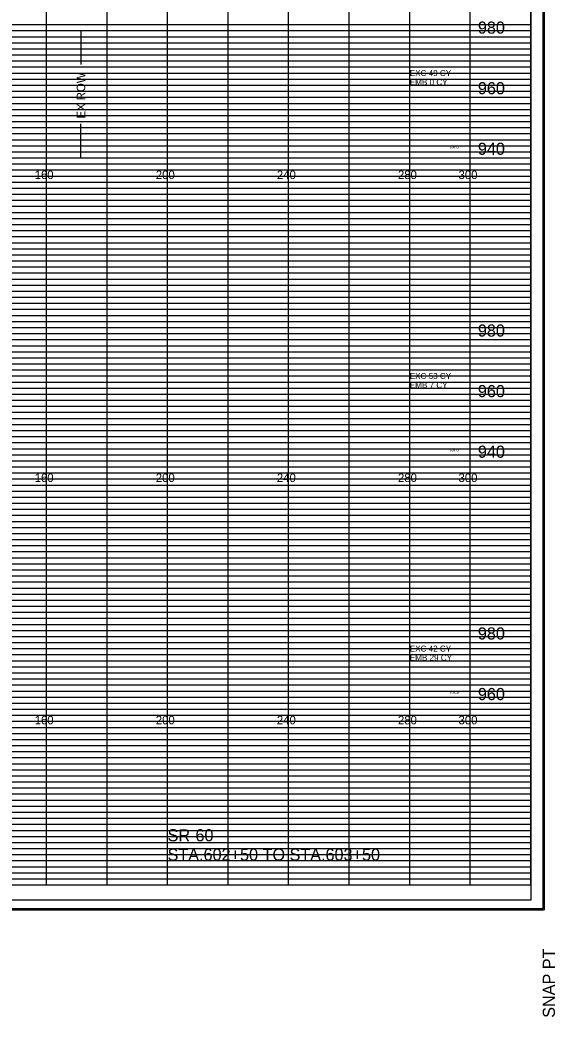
# Model space of a CAD drawing. Extents: x 2313580 to 2322968, y 282099 to 303247.
# Drawn here: x 2318934.9 to 2319111.7, y 287544 to 287873.2 of the extents above; entities that cross this region are included whole.
import ezdxf

# ---------------------------------------------------------------- set-up
doc = ezdxf.new("R2010")
doc.units = 0
for name, color, linetype in [('DESIGN - EARTHWORK - Excavation Limit Lines', 7, 'Continuous'), ('DESIGN - SHEET - Corner Text', 7, 'Continuous'), ('DESIGN - SHEET - Light Grid', 7, 'Continuous'), ('DESIGN - SHEET - Linework', 7, 'Continuous'), ('DESIGN - SHEET - Plot Shape', 7, 'Continuous'), ('DESIGN - TYPICAL - Text', 7, 'Continuous'), ('Prop_ CL text', 7, 'Continuous'), ('SURVEY - PROPERTY - ROW Lines Text', 7, 'Continuous')]:
    doc.layers.add(name, color=color, linetype=linetype)

msp = doc.modelspace()

# ---------------------------------------------------------------- linework, layer by layer
at = {"layer": 'DESIGN - SHEET - Light Grid'}
for p, q in [((2318783.68, 287871.67), (2318943.68, 287871.67)), ((2318783.68, 287869.67), (2318943.68, 287869.67)), ((2318943.68, 287871.67), (2319103.68, 287871.67)), ((2318943.68, 287869.67), (2319103.68, 287869.67)), ((2318783.68, 287865.67), (2318943.68, 287865.67)), ((2318783.68, 287863.67), (2318943.68, 287863.67)), ((2318943.68, 287865.67), (2319103.68, 287865.67)), ((2318943.68, 287863.67), (2319103.68, 287863.67)), ((2318783.68, 287861.67), (2318943.68, 287861.67)), ((2318783.68, 287859.67), (2318943.68, 287859.67)), ((2318943.68, 287861.67), (2319103.68, 287861.67)), ((2318943.68, 287859.67), (2319103.68, 287859.67)), ((2318783.68, 287857.67), (2318943.68, 287857.67)), ((2318943.68, 287857.67), (2319103.68, 287857.67)), ((2318783.68, 287855.67), (2318943.68, 287855.67)), ((2318783.68, 287853.67), (2318943.68, 287853.67)), ((2318943.68, 287855.67), (2319103.68, 287855.67)), ((2318943.68, 287853.67), (2319103.68, 287853.67)), ((2318783.68, 287851.67), (2318943.68, 287851.67)), ((2318783.68, 287849.67), (2318943.68, 287849.67)), ((2318943.68, 287851.67), (2319103.68, 287851.67)), ((2318943.68, 287849.67), (2319103.68, 287849.67)), ((2318783.68, 287845.67), (2318943.68, 287845.67)), ((2318783.68, 287843.67), (2318943.68, 287843.67)), ((2318943.68, 287845.67), (2319103.68, 287845.67)), ((2318943.68, 287843.67), (2319103.68, 287843.67)), ((2318783.68, 287841.67), (2318943.68, 287841.67)), ((2318943.68, 287841.67), (2319103.68, 287841.67)), ((2318783.68, 287839.67), (2318943.68, 287839.67)), ((2318783.68, 287837.67), (2318943.68, 287837.67)), ((2318943.68, 287839.67), (2319103.68, 287839.67)), ((2318943.68, 287837.67), (2319103.68, 287837.67)), ((2318783.68, 287835.67), (2318943.68, 287835.67)), ((2318783.68, 287833.67), (2318943.68, 287833.67)), ((2318943.68, 287835.67), (2319103.68, 287835.67)), ((2318943.68, 287833.67), (2319103.68, 287833.67)), ((2318783.68, 287831.67), (2318943.68, 287831.67)), ((2318943.68, 287831.67), (2319103.68, 287831.67)), ((2318783.68, 287829.67), (2318943.68, 287829.67)), ((2318943.68, 287829.67), (2319103.68, 287829.67)), ((2318783.68, 287825.67), (2318943.68, 287825.67)), ((2318783.68, 287823.67), (2318943.68, 287823.67)), ((2318943.68, 287825.67), (2319103.68, 287825.67)), ((2318943.68, 287823.67), (2319103.68, 287823.67)), ((2318783.68, 287821.67), (2318943.68, 287821.67)), ((2318943.68, 287821.67), (2319103.68, 287821.67)), ((2318783.68, 287819.67), (2318943.68, 287819.67)), ((2318783.68, 287817.67), (2318943.68, 287817.67)), ((2318943.68, 287819.67), (2319103.68, 287819.67)), ((2318943.68, 287817.67), (2319103.68, 287817.67)), ((2318783.68, 287815.67), (2318943.68, 287815.67)), ((2318783.68, 287813.67), (2318943.68, 287813.67)), ((2318943.68, 287815.67), (2319103.68, 287815.67)), ((2318943.68, 287813.67), (2319103.68, 287813.67)), ((2318783.68, 287811.67), (2318943.68, 287811.67)), ((2318943.68, 287811.67), (2319103.68, 287811.67)), ((2318783.68, 287809.67), (2318943.68, 287809.67)), ((2318943.68, 287809.67), (2319103.68, 287809.67)), ((2318783.68, 287805.67), (2318943.68, 287805.67)), ((2318783.68, 287803.67), (2318943.68, 287803.67)), ((2318943.68, 287805.67), (2319103.68, 287805.67)), ((2318943.68, 287803.67), (2319103.68, 287803.67)), ((2318783.68, 287801.67), (2318943.68, 287801.67)), ((2318943.68, 287801.67), (2319103.68, 287801.67)), ((2318783.68, 287799.67), (2318943.68, 287799.67)), ((2318783.68, 287797.67), (2318943.68, 287797.67)), ((2318943.68, 287799.67), (2319103.68, 287799.67)), ((2318943.68, 287797.67), (2319103.68, 287797.67)), ((2318783.68, 287795.67), (2318943.68, 287795.67)), ((2318783.68, 287793.67), (2318943.68, 287793.67)), ((2318943.68, 287795.67), (2319103.68, 287795.67)), ((2318943.68, 287793.67), (2319103.68, 287793.67)), ((2318783.68, 287791.67), (2318943.68, 287791.67)), ((2318943.68, 287791.67), (2319103.68, 287791.67)), ((2318783.68, 287789.67), (2318943.68, 287789.67)), ((2318943.68, 287789.67), (2319103.68, 287789.67)), ((2318783.68, 287785.67), (2318943.68, 287785.67)), ((2318943.68, 287785.67), (2319103.68, 287785.67)), ((2318783.68, 287783.67), (2318943.68, 287783.67)), ((2318783.68, 287781.67), (2318943.68, 287781.67)), ((2318943.68, 287783.67), (2319103.68, 287783.67)), ((2318943.68, 287781.67), (2319103.68, 287781.67)), ((2318783.68, 287779.67), (2318943.68, 287779.67)), ((2318783.68, 287777.67), (2318943.68, 287777.67)), ((2318943.68, 287779.67), (2319103.68, 287779.67)), ((2318943.68, 287777.67), (2319103.68, 287777.67)), ((2318783.68, 287775.67), (2318943.68, 287775.67)), ((2318943.68, 287775.67), (2319103.68, 287775.67)), ((2318783.68, 287773.67), (2318943.68, 287773.67)), ((2318783.68, 287771.67), (2318943.68, 287771.67)), ((2318943.68, 287773.67), (2319103.68, 287773.67)), ((2318943.68, 287771.67), (2319103.68, 287771.67)), ((2318783.68, 287769.67), (2318943.68, 287769.67)), ((2318943.68, 287769.67), (2319103.68, 287769.67)), ((2318783.68, 287765.67), (2318943.68, 287765.67)), ((2318943.68, 287765.67), (2319103.68, 287765.67)), ((2318783.68, 287763.67), (2318943.68, 287763.67)), ((2318783.68, 287761.67), (2318943.68, 287761.67)), ((2318943.68, 287763.67), (2319103.68, 287763.67)), ((2318943.68, 287761.67), (2319103.68, 287761.67)), ((2318783.68, 287759.67), (2318943.68, 287759.67)), ((2318783.68, 287757.67), (2318943.68, 287757.67)), ((2318943.68, 287759.67), (2319103.68, 287759.67)), ((2318943.68, 287757.67), (2319103.68, 287757.67)), ((2318783.68, 287755.67), (2318943.68, 287755.67)), ((2318943.68, 287755.67), (2319103.68, 287755.67)), ((2318783.68, 287753.67), (2318943.68, 287753.67)), ((2318783.68, 287751.67), (2318943.68, 287751.67)), ((2318943.68, 287753.67), (2319103.68, 287753.67)), ((2318943.68, 287751.67), (2319103.68, 287751.67)), ((2318783.68, 287749.67), (2318943.68, 287749.67)), ((2318943.68, 287749.67), (2319103.68, 287749.67)), ((2318783.68, 287745.67), (2318943.68, 287745.67)), ((2318943.68, 287745.67), (2319103.68, 287745.67)), ((2318783.68, 287743.67), (2318943.68, 287743.67)), ((2318783.68, 287741.67), (2318943.68, 287741.67)), ((2318943.68, 287743.67), (2319103.68, 287743.67)), ((2318943.68, 287741.67), (2319103.68, 287741.67)), ((2318783.68, 287739.67), (2318943.68, 287739.67)), ((2318783.68, 287737.67), (2318943.68, 287737.67)), ((2318943.68, 287739.67), (2319103.68, 287739.67)), ((2318943.68, 287737.67), (2319103.68, 287737.67)), ((2318783.68, 287735.67), (2318943.68, 287735.67)), ((2318943.68, 287735.67), (2319103.68, 287735.67)), ((2318783.68, 287733.67), (2318943.68, 287733.67)), ((2318783.68, 287731.67), (2318943.68, 287731.67)), ((2318943.68, 287733.67), (2319103.68, 287733.67)), ((2318943.68, 287731.67), (2319103.68, 287731.67)), ((2318783.68, 287729.67), (2318943.68, 287729.67)), ((2318943.68, 287729.67), (2319103.68, 287729.67)), ((2318783.68, 287725.67), (2318943.68, 287725.67)), ((2318943.68, 287725.67), (2319103.68, 287725.67)), ((2318783.68, 287723.67), (2318943.68, 287723.67)), ((2318783.68, 287721.67), (2318943.68, 287721.67)), ((2318943.68, 287723.67), (2319103.68, 287723.67)), ((2318943.68, 287721.67), (2319103.68, 287721.67)), ((2318783.68, 287719.67), (2318943.68, 287719.67)), ((2318943.68, 287719.67), (2319103.68, 287719.67)), ((2318783.68, 287717.67), (2318943.68, 287717.67)), ((2318783.68, 287715.67), (2318943.68, 287715.67)), ((2318943.68, 287717.67), (2319103.68, 287717.67)), ((2318943.68, 287715.67), (2319103.68, 287715.67)), ((2318783.68, 287713.67), (2318943.68, 287713.67)), ((2318783.68, 287711.67), (2318943.68, 287711.67)), ((2318943.68, 287713.67), (2319103.68, 287713.67)), ((2318943.68, 287711.67), (2319103.68, 287711.67)), ((2318783.68, 287709.67), (2318943.68, 287709.67)), ((2318943.68, 287709.67), (2319103.68, 287709.67)), ((2318783.68, 287705.67), (2318943.68, 287705.67)), ((2318943.68, 287705.67), (2319103.68, 287705.67)), ((2318783.68, 287703.67), (2318943.68, 287703.67)), ((2318783.68, 287701.67), (2318943.68, 287701.67)), ((2318943.68, 287703.67), (2319103.68, 287703.67)), ((2318943.68, 287701.67), (2319103.68, 287701.67)), ((2318783.68, 287699.67), (2318943.68, 287699.67)), ((2318943.68, 287699.67), (2319103.68, 287699.67)), ((2318783.68, 287697.67), (2318943.68, 287697.67)), ((2318783.68, 287695.67), (2318943.68, 287695.67)), ((2318943.68, 287697.67), (2319103.68, 287697.67)), ((2318943.68, 287695.67), (2319103.68, 287695.67)), ((2318783.68, 287693.67), (2318943.68, 287693.67)), ((2318783.68, 287691.67), (2318943.68, 287691.67)), ((2318943.68, 287693.67), (2319103.68, 287693.67)), ((2318943.68, 287691.67), (2319103.68, 287691.67)), ((2318783.68, 287689.67), (2318943.68, 287689.67)), ((2318943.68, 287689.67), (2319103.68, 287689.67)), ((2318783.68, 287685.67), (2318943.68, 287685.67)), ((2318943.68, 287685.67), (2319103.68, 287685.67)), ((2318783.68, 287683.67), (2318943.68, 287683.67)), ((2318943.68, 287683.67), (2319103.68, 287683.67)), ((2318783.68, 287681.67), (2318943.68, 287681.67)), ((2318783.68, 287679.67), (2318943.68, 287679.67)), ((2318943.68, 287681.67), (2319103.68, 287681.67)), ((2318943.68, 287679.67), (2319103.68, 287679.67)), ((2318783.68, 287677.67), (2318943.68, 287677.67)), ((2318783.68, 287675.67), (2318943.68, 287675.67)), ((2318943.68, 287677.67), (2319103.68, 287677.67)), ((2318943.68, 287675.67), (2319103.68, 287675.67)), ((2318783.68, 287673.67), (2318943.68, 287673.67)), ((2318943.68, 287673.67), (2319103.68, 287673.67)), ((2318783.68, 287671.67), (2318943.68, 287671.67)), ((2318783.68, 287669.67), (2318943.68, 287669.67)), ((2318943.68, 287671.67), (2319103.68, 287671.67)), ((2318943.68, 287669.67), (2319103.68, 287669.67)), ((2318783.68, 287665.67), (2318943.68, 287665.67)), ((2318943.68, 287665.67), (2319103.68, 287665.67)), ((2318783.68, 287663.67), (2318943.68, 287663.67)), ((2318943.68, 287663.67), (2319103.68, 287663.67)), ((2318783.68, 287661.67), (2318943.68, 287661.67)), ((2318783.68, 287659.67), (2318943.68, 287659.67)), ((2318943.68, 287661.67), (2319103.68, 287661.67)), ((2318943.68, 287659.67), (2319103.68, 287659.67)), ((2318783.68, 287657.67), (2318943.68, 287657.67)), ((2318783.68, 287655.67), (2318943.68, 287655.67)), ((2318943.68, 287657.67), (2319103.68, 287657.67)), ((2318943.68, 287655.67), (2319103.68, 287655.67)), ((2318783.68, 287653.67), (2318943.68, 287653.67)), ((2318943.68, 287653.67), (2319103.68, 287653.67)), ((2318783.68, 287651.67), (2318943.68, 287651.67)), ((2318783.68, 287649.67), (2318943.68, 287649.67)), ((2318943.68, 287651.67), (2319103.68, 287651.67)), ((2318943.68, 287649.67), (2319103.68, 287649.67)), ((2318783.68, 287645.67), (2318943.68, 287645.67)), ((2318943.68, 287645.67), (2319103.68, 287645.67)), ((2318783.68, 287643.67), (2318943.68, 287643.67)), ((2318943.68, 287643.67), (2319103.68, 287643.67)), ((2318783.68, 287641.67), (2318943.68, 287641.67)), ((2318783.68, 287639.67), (2318943.68, 287639.67)), ((2318943.68, 287641.67), (2319103.68, 287641.67)), ((2318943.68, 287639.67), (2319103.68, 287639.67)), ((2318783.68, 287637.67), (2318943.68, 287637.67)), ((2318783.68, 287635.67), (2318943.68, 287635.67)), ((2318943.68, 287637.67), (2319103.68, 287637.67)), ((2318943.68, 287635.67), (2319103.68, 287635.67)), ((2318783.68, 287633.67), (2318943.68, 287633.67)), ((2318943.68, 287633.67), (2319103.68, 287633.67)), ((2318783.68, 287631.67), (2318943.68, 287631.67)), ((2318783.68, 287629.67), (2318943.68, 287629.67)), ((2318943.68, 287631.67), (2319103.68, 287631.67)), ((2318943.68, 287629.67), (2319103.68, 287629.67)), ((2318783.68, 287625.67), (2318943.68, 287625.67)), ((2318783.68, 287623.67), (2318943.68, 287623.67)), ((2318943.68, 287625.67), (2319103.68, 287625.67)), ((2318943.68, 287623.67), (2319103.68, 287623.67)), ((2318783.68, 287621.67), (2318943.68, 287621.67)), ((2318783.68, 287619.67), (2318943.68, 287619.67)), ((2318943.68, 287621.67), (2319103.68, 287621.67)), ((2318943.68, 287619.67), (2319103.68, 287619.67)), ((2318783.68, 287617.67), (2318943.68, 287617.67)), ((2318943.68, 287617.67), (2319103.68, 287617.67)), ((2318783.68, 287615.67), (2318943.68, 287615.67)), ((2318783.68, 287613.67), (2318943.68, 287613.67)), ((2318943.68, 287615.67), (2319103.68, 287615.67)), ((2318943.68, 287613.67), (2319103.68, 287613.67)), ((2318783.68, 287611.67), (2318943.68, 287611.67)), ((2318783.68, 287609.67), (2318943.68, 287609.67)), ((2318943.68, 287611.67), (2319103.68, 287611.67)), ((2318943.68, 287609.67), (2319103.68, 287609.67)), ((2318783.68, 287605.67), (2318943.68, 287605.67)), ((2318783.68, 287603.67), (2318943.68, 287603.67)), ((2318943.68, 287605.67), (2319103.68, 287605.67)), ((2318943.68, 287603.67), (2319103.68, 287603.67)), ((2318783.68, 287601.67), (2318943.68, 287601.67)), ((2318783.68, 287599.67), (2318943.68, 287599.67)), ((2318943.68, 287601.67), (2319103.68, 287601.67)), ((2318943.68, 287599.67), (2319103.68, 287599.67)), ((2318783.68, 287597.67), (2318943.68, 287597.67)), ((2318943.68, 287597.67), (2319103.68, 287597.67)), ((2318783.68, 287595.67), (2318943.68, 287595.67)), ((2318783.68, 287593.67), (2318943.68, 287593.67)), ((2318943.68, 287595.67), (2319103.68, 287595.67)), ((2318943.68, 287593.67), (2319103.68, 287593.67)), ((2318783.68, 287591.67), (2318943.68, 287591.67)), ((2318783.68, 287589.67), (2318943.68, 287589.67)), ((2318943.68, 287591.67), (2319103.68, 287591.67)), ((2318943.68, 287589.67), (2319103.68, 287589.67))]:
    msp.add_line(p, q, dxfattribs=at)
at = {"layer": 'DESIGN - SHEET - Linework'}
for p, q in [((2319108.02, 288015.95), (2319108.02, 287579.39)), ((2318943.68, 287587.67), (2318943.68, 288007.67)), ((2318963.68, 287587.67), (2318963.68, 288007.67)), ((2318983.68, 287587.67), (2318983.68, 288007.67)), ((2319003.68, 287587.67), (2319003.68, 288007.67)), ((2319023.68, 287587.67), (2319023.68, 287987.67)), ((2319043.68, 287587.67), (2319043.68, 287987.67)), ((2319063.68, 287587.67), (2319063.68, 287987.67)), ((2319083.68, 287587.67), (2319083.68, 287987.67)), ((2318463.68, 287867.67), (2319103.68, 287867.67)), ((2318463.68, 287847.67), (2319103.68, 287847.67)), ((2318463.68, 287827.67), (2319103.68, 287827.67)), ((2318463.68, 287807.67), (2319103.68, 287807.67)), ((2318463.68, 287787.67), (2319103.68, 287787.67)), ((2318463.68, 287767.67), (2319103.68, 287767.67)), ((2318463.68, 287747.67), (2319103.68, 287747.67)), ((2318463.68, 287727.67), (2319103.68, 287727.67)), ((2318463.68, 287707.67), (2319103.68, 287707.67)), ((2318463.68, 287687.67), (2319103.68, 287687.67)), ((2318463.68, 287667.67), (2319103.68, 287667.67)), ((2318463.68, 287647.67), (2319103.68, 287647.67)), ((2318463.68, 287627.67), (2319103.68, 287627.67)), ((2318463.68, 287607.67), (2319103.68, 287607.67)), ((2318427.22, 287579.39), (2319108.02, 287579.39))]:
    msp.add_line(p, q, dxfattribs=at)
msp.add_lwpolyline([(2318463.68, 288007.67), (2318463.68, 287587.67), (2319103.68, 287587.67), (2319103.68, 288007.67), (2318463.68, 288007.67)], dxfattribs=at)
at = {"layer": 'DESIGN - SHEET - Plot Shape'}
for points in [[(2318427.62, 288015.55), (2319107.62, 288015.55), (2319107.62, 287579.79), (2318427.62, 287579.79)], [(2318446.68, 288007.67), (2319103.68, 288007.67), (2319103.68, 287582.67), (2318446.68, 287582.67)]]:
    msp.add_lwpolyline(points, close=True, dxfattribs=at)
at = {"layer": 'SURVEY - PROPERTY - ROW Lines Text'}
for p, q in [((2318955.07, 287869.67), (2318955.07, 287858.47)), ((2318955.07, 287827.67), (2318955.07, 287838.87))]:
    msp.add_line(p, q, dxfattribs=at)

# ---------------------------------------------------------------- texts
at = {"layer": 'DESIGN - EARTHWORK - Excavation Limit Lines'}
for s, p in [('EXC 49 CY', (2319063.68, 287854.67)), ('EMB 0 CY', (2319063.68, 287851.67)), ('EXC 53 CY', (2319063.68, 287754.67)), ('EMB 7 CY', (2319063.68, 287751.67)), ('EXC 42 CY', (2319063.68, 287664.67)), ('EMB 29 CY', (2319063.68, 287661.67))]:
    msp.add_text(s, height=2, dxfattribs=at).set_placement(p)
at = {"layer": 'DESIGN - SHEET - Corner Text'}
msp.add_text('SNAP PT  ', height=4, rotation=90, dxfattribs=at).set_placement((2319111.62, 287543.79))
at = {"layer": 'DESIGN - TYPICAL - Text'}
for s, height, p in [('980', 4, (2319086.18, 287868.67)), ('960', 4, (2319086.18, 287848.67)), ('940', 4, (2319086.18, 287828.67)), ('160', 2.8, (2318939.79, 287820.67)), ('200', 2.8, (2318979.79, 287820.67)), ('240', 2.8, (2319019.79, 287820.67)), ('280', 2.8, (2319059.79, 287820.67)), ('300', 2.8, (2319079.79, 287820.67)), ('980', 4, (2319086.18, 287768.67)), ('960', 4, (2319086.18, 287748.67)), ('940', 4, (2319086.18, 287728.67)), ('160', 2.8, (2318939.79, 287720.67)), ('200', 2.8, (2318979.79, 287720.67)), ('240', 2.8, (2319019.79, 287720.67)), ('280', 2.8, (2319059.79, 287720.67)), ('300', 2.8, (2319079.79, 287720.67)), ('980', 4, (2319086.18, 287668.67)), ('960', 4, (2319086.18, 287648.67)), ('160', 2.8, (2318939.79, 287640.67)), ('200', 2.8, (2318979.79, 287640.67)), ('240', 2.8, (2319019.79, 287640.67)), ('280', 2.8, (2319059.79, 287640.67)), ('300', 2.8, (2319079.79, 287640.67)), ('SR-60', 4, (2318983.68, 287602.05)), ('STA.602+50 TO STA.603+50', 4, (2318983.68, 287595.67))]:
    msp.add_text(s, height=height, dxfattribs=at).set_placement(p)
at = {"layer": 'Prop_ CL text'}
for s, p in [('FA:0', (2319076.92, 287830.67)), ('FA:0', (2319076.92, 287730.67)), ('FA:8', (2319076.99, 287650.67))]:
    msp.add_text(s, height=1, dxfattribs=at).set_placement(p)
at = {"layer": 'SURVEY - PROPERTY - ROW Lines Text'}
msp.add_text('EX ROW', height=2.8, rotation=90, dxfattribs=at).set_placement((2318956.47, 287840.67))

doc.saveas('drawing.dxf')
